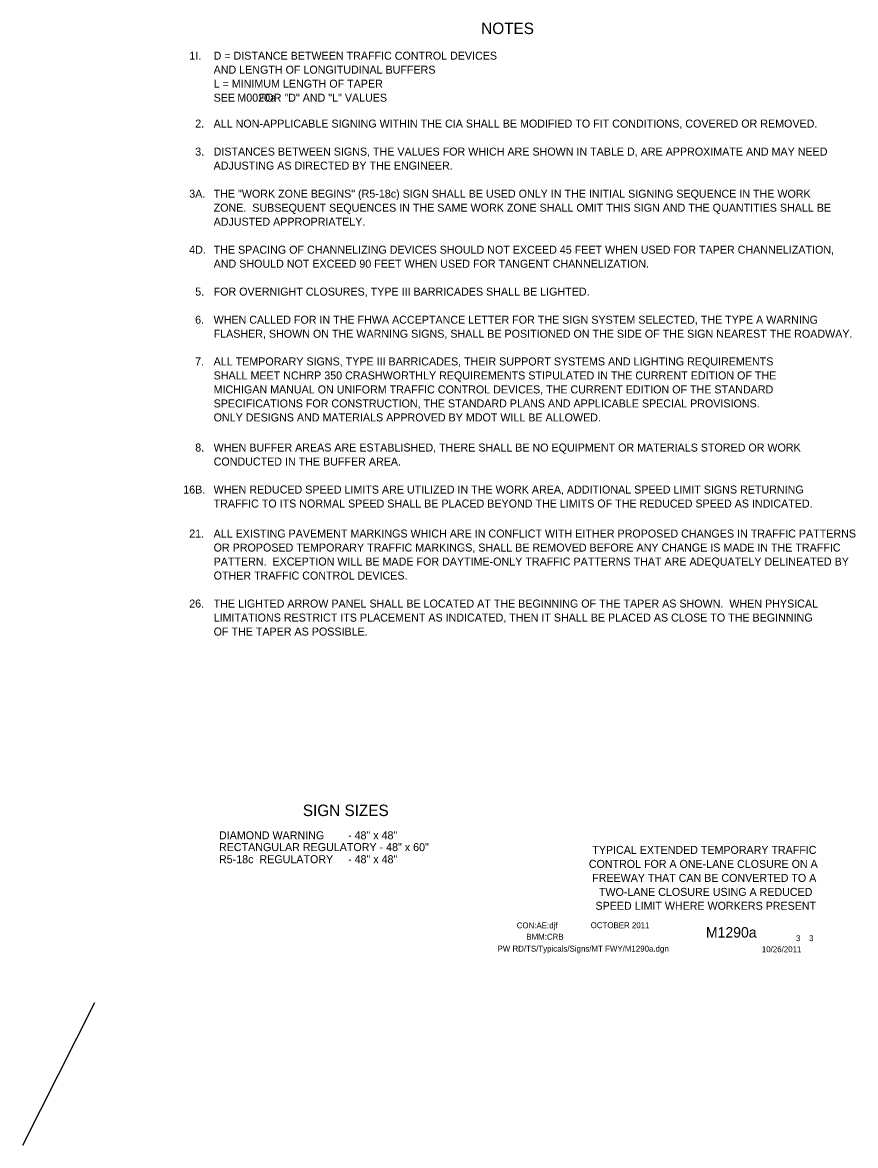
# Model space of a CAD drawing. Extents: x 16590 to 19504, y 5703 to 6974.
# Drawn here: x 18630 to 19504, y 5730 to 6909 of the extents above; entities that cross this region are included whole.
import ezdxf

# ---------------------------------------------------------------- set-up
doc = ezdxf.new("R2010")
doc.units = 0
for name, color, linetype in [('BORDER', 7, 'Continuous'), ('BORDER_SIGNAL_WO', 7, 'Continuous'), ('TYPICAL_TEXT_DIMEN_PR', 7, 'Continuous')]:
    doc.layers.add(name, color=color, linetype=linetype)

msp = doc.modelspace()

# ---------------------------------------------------------------- linework, layer by layer
at = {"layer": 'TYPICAL_TEXT_DIMEN_PR'}
msp.add_line((18705.8, 5880), (18630.1, 5730.1), dxfattribs=at)

# ---------------------------------------------------------------- texts
at = {"layer": 'BORDER'}
for s, p in [('TYPICAL EXTENDED TEMPORARY TRAFFIC', (19228.1, 6036.3)), ('CONTROL FOR A ONE-LANE CLOSURE ON A', (19224.4, 6021.6)), ('FREEWAY THAT CAN BE CONVERTED TO A', (19227.9, 6006.9)), ('TWO-LANE CLOSURE USING A REDUCED', (19235, 5992.2)), ('SPEED LIMIT WHERE WORKERS PRESENT', (19231.4, 5977.6))]:
    msp.add_text(s, height=8.373, dxfattribs=at).set_placement(p)
at = {"layer": 'BORDER_SIGNAL_WO'}
for s, height, p in [('CON:AE:djf  ', 6.2, (19148.7, 5958.1)), ('    OCTOBER 2011    ', 6.2, (19217.1, 5958.3)), ('    M1290a   ', 11, (19330.9, 5948.4)), ('BMM:CRB   ', 6.2, (19158.8, 5946.2)), (' 3    3 ', 6.2, (19439.4, 5944.7)), ('PW RD/TS/Typicals/Signs/MT FWY/M1290a.dgn      ', 6.2, (19128.6, 5933.7)), ('10/26/2011    ', 6.2, (19405.9, 5933.1))]:
    msp.add_text(s, height=height, dxfattribs=at).set_placement(p)
at = {"layer": 'TYPICAL_TEXT_DIMEN_PR'}
for s, height, p in [('NOTES', 12, (19111.5, 6897)), ('1I.', 8.4, (18805.2, 6870.1)), ('D = DISTANCE BETWEEN TRAFFIC CONTROL DEVICES', 8.4, (18830.7, 6870.1)), ('AND LENGTH OF LONGITUDINAL BUFFERS', 8.4, (18830.7, 6855.4)), ('L = MINIMUM LENGTH OF TAPER', 8.4, (18830.7, 6840.7)), ('SEE        FOR "D" AND "L" VALUES', 8.4, (18830.7, 6826)), ('M0020a', 8.4, (18855.6, 6826)), ('2.', 8.4, (18811.4, 6798.8)), ('ALL NON-APPLICABLE SIGNING WITHIN THE CIA SHALL BE MODIFIED TO FIT CONDITIONS, COVERED OR REMOVED.', 8.4, (18830.7, 6798.8)), ('3.', 8.4, (18811.4, 6769.4)), ('DISTANCES BETWEEN SIGNS, THE VALUES FOR WHICH ARE SHOWN IN TABLE D, ARE APPROXIMATE AND MAY NEED', 8.4, (18830.7, 6769.4)), ('ADJUSTING AS DIRECTED BY THE ENGINEER.', 8.4, (18830.7, 6754.7)), ('3A.', 8.4, (18805.1, 6725.2)), ('THE "WORK ZONE BEGINS" (R5-18c) SIGN SHALL BE USED ONLY IN THE INITIAL SIGNING SEQUENCE IN THE WORK', 8.4, (18830.7, 6725.2)), ('ZONE.  SUBSEQUENT SEQUENCES IN THE SAME WORK ZONE SHALL OMIT THIS SIGN AND THE QUANTITIES SHALL BE', 8.4, (18830.7, 6710.5)), ('ADJUSTED APPROPRIATELY.', 8.4, (18830.7, 6695.8)), ('4D.', 8.4, (18805, 6666.4)), ('THE SPACING OF CHANNELIZING DEVICES SHOULD NOT EXCEED 45 FEET WHEN USED FOR TAPER CHANNELIZATION,', 8.4, (18830.7, 6666.4)), ('AND SHOULD NOT EXCEED 90 FEET WHEN USED FOR TANGENT CHANNELIZATION.', 8.4, (18830.7, 6651.7)), ('5.', 8.4, (18811.4, 6622.4)), ('FOR OVERNIGHT CLOSURES, TYPE III BARRICADES SHALL BE LIGHTED. ', 8.4, (18830.7, 6622.4)), ('6.', 8.4, (18811.3, 6592.9)), ('WHEN CALLED FOR IN THE FHWA ACCEPTANCE LETTER FOR THE SIGN SYSTEM SELECTED, THE TYPE A WARNING ', 8.4, (18830.7, 6592.9)), ('FLASHER, SHOWN ON THE WARNING SIGNS, SHALL BE POSITIONED ON THE SIDE OF THE SIGN NEAREST THE ROADWAY.', 8.4, (18830.7, 6578.2)), ('7.', 8.4, (18811.3, 6549.1)), ('ALL TEMPORARY SIGNS, TYPE III BARRICADES, THEIR SUPPORT SYSTEMS AND LIGHTING REQUIREMENTS', 8.4, (18830.7, 6549.1)), ('SHALL MEET NCHRP 350 CRASHWORTHLY REQUIREMENTS STIPULATED IN THE CURRENT EDITION OF THE', 8.4, (18830.7, 6534.4)), ('MICHIGAN MANUAL ON UNIFORM TRAFFIC CONTROL DEVICES, THE CURRENT EDITION OF THE STANDARD', 8.4, (18830.7, 6519.7)), ('SPECIFICATIONS FOR CONSTRUCTION, THE STANDARD PLANS AND APPLICABLE SPECIAL PROVISIONS.', 8.4, (18830.7, 6505)), ('ONLY DESIGNS AND MATERIALS APPROVED BY MDOT WILL BE ALLOWED.', 8.4, (18830.7, 6490.3)), ('8.', 8.4, (18811.4, 6458.7)), ('WHEN BUFFER AREAS ARE ESTABLISHED, THERE SHALL BE NO EQUIPMENT OR MATERIALS STORED OR WORK     ', 8.4, (18830.7, 6458.7)), ('CONDUCTED IN THE BUFFER AREA.', 8.4, (18830.7, 6444)), ('16B.', 8.4, (18798.8, 6414.6)), ('WHEN REDUCED SPEED LIMITS ARE UTILIZED IN THE WORK AREA, ADDITIONAL SPEED LIMIT SIGNS RETURNING', 8.4, (18830.7, 6414.6)), ('TRAFFIC TO ITS NORMAL SPEED SHALL BE PLACED BEYOND THE LIMITS OF THE REDUCED SPEED AS INDICATED.', 8.4, (18830.7, 6399.9)), ('21.', 8.4, (18805.1, 6368.4)), ('ALL EXISTING PAVEMENT MARKINGS WHICH ARE IN CONFLICT WITH EITHER PROPOSED CHANGES IN TRAFFIC PATTERNS', 8.4, (18830.7, 6368.4)), ('OR PROPOSED TEMPORARY TRAFFIC MARKINGS, SHALL BE REMOVED BEFORE ANY CHANGE IS MADE IN THE TRAFFIC', 8.4, (18830.7, 6353.7)), ('PATTERN.  EXCEPTION WILL BE MADE FOR DAYTIME-ONLY TRAFFIC PATTERNS THAT ARE ADEQUATELY DELINEATED BY', 8.4, (18830.7, 6339)), ('OTHER TRAFFIC CONTROL DEVICES.', 8.4, (18830.7, 6324.3)), ('26.', 8.4, (18805.1, 6294.9)), ('THE LIGHTED ARROW PANEL SHALL BE LOCATED AT THE BEGINNING OF THE TAPER AS SHOWN.  WHEN PHYSICAL', 8.4, (18830.7, 6294.9)), ('LIMITATIONS RESTRICT ITS PLACEMENT AS INDICATED, THEN IT SHALL BE PLACED AS CLOSE TO THE BEGINNING', 8.4, (18830.7, 6280.2)), ('OF THE TAPER AS POSSIBLE.', 8.4, (18830.7, 6265.5)), ('SIGN SIZES', 12, (18924.3, 6076)), ('DIAMOND WARNING        - 48" x 48"', 8.4, (18836.3, 6051.6)), ('RECTANGULAR REGULATORY - 48" x 60"', 8.4, (18836.3, 6039.2)), ('R5-18c  REGULATORY     - 48" x 48"', 8.4, (18836.3, 6026.5))]:
    msp.add_text(s, height=height, dxfattribs=at).set_placement(p)

doc.saveas('drawing.dxf')
